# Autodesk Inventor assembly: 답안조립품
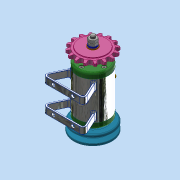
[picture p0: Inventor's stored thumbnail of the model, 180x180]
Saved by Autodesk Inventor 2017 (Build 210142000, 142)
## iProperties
Part Number: 답안조립품
Material: 일반
Document SubType Name: Assembly
Designer: user
Author: user
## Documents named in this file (16)
- C:\Users\user\Desktop\711206V1014\답안조립품.iam
- C:\Users\user\Desktop\711206V1014\V벨트풀리.ipt
- C:\Users\user\Desktop\711206V1014\너트 M8.ipt
- C:\Users\user\Desktop\711206V1014\니플 M6 x 0.75.ipt
- C:\Users\user\Desktop\711206V1014\베어링 6002.ipt
- C:\Users\user\Desktop\711206V1014\본체.ipt
- C:\Users\user\Desktop\711206V1014\볼트 M4 x 12.ipt
- C:\Users\user\Desktop\711206V1014\볼트 M6 x 8.ipt
- C:\Users\user\Desktop\711206V1014\스프로킷.ipt
- C:\Users\user\Desktop\711206V1014\스프링와셔 8.ipt
- C:\Users\user\Desktop\711206V1014\오일 실 15 x 25 x 7.ipt
- C:\Users\user\Desktop\711206V1014\와셔 6 x 11.5.ipt
- C:\Users\user\Desktop\711206V1014\와셔 8 x 17.ipt
- C:\Users\user\Desktop\711206V1014\축.ipt
- C:\Users\user\Desktop\711206V1014\커버.ipt
- C:\Users\user\Desktop\711206V1014\키 3 x 3.ipt
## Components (11 placed, 3 different names)
1. V벨트풀리:1
2. KS B 2023 6002 - 15 x 32 x 9:1
3. KS B 2023 6002 - 15 x 32 x 9:2
4. ISO 4762 M4 x 12:1
5. ISO 4762 M4 x 12:3
6. ISO 4762 M4 x 12:4
7. ISO 4762 M4 x 12:5
8. ISO 4762 M4 x 12:2
9. ISO 4762 M4 x 12:6
10. ISO 4762 M4 x 12:7
11. ISO 4762 M4 x 12:8
